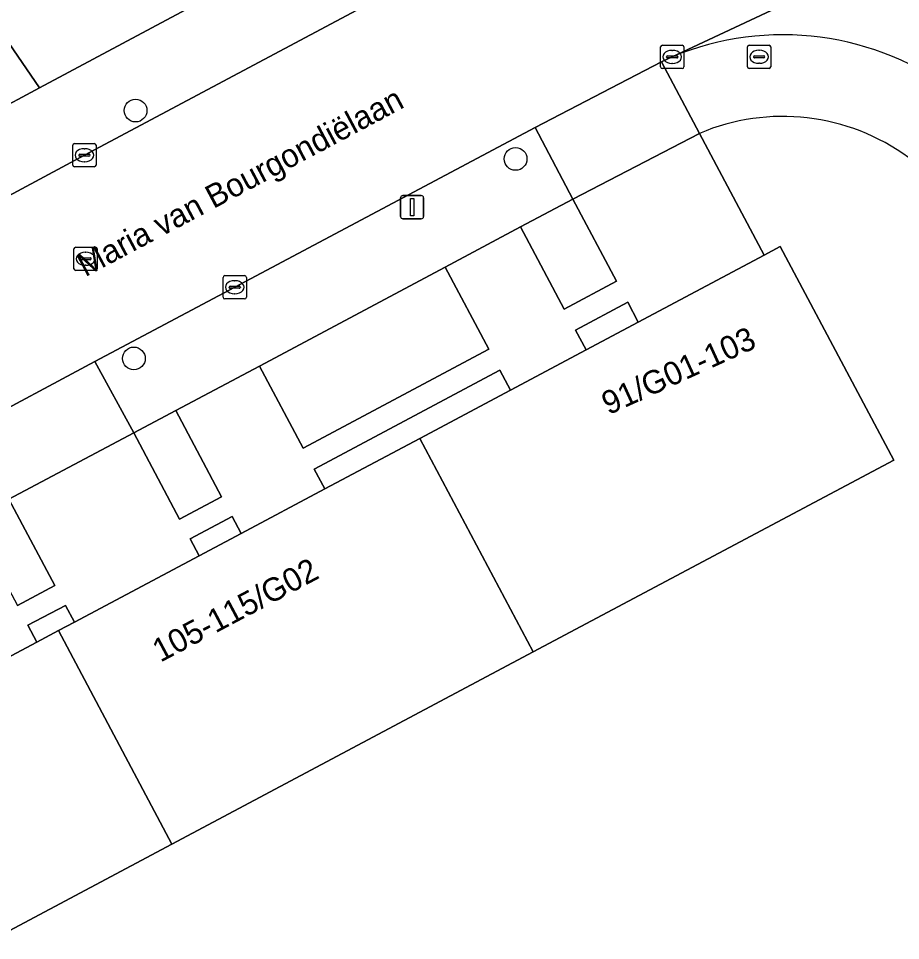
# Model space of a CAD drawing. Extents: x 159674 to 160531, y 382172 to 382904.
# Drawn here: x 159928.92 to 159966.84, y 382366.41 to 382406.07 of the extents above; entities that cross this region are included whole.
import ezdxf

# ---------------------------------------------------------------- set-up
doc = ezdxf.new("R2010")
doc.units = 0
for name, color, linetype in [('IMGEO_Boom', 7, 'Continuous'), ('IMGEO_Brandkraan', 7, 'Continuous'), ('IMGEO_Groenvoorziening', 7, 'Continuous'), ('IMGEO_Kolk', 7, 'Continuous'), ('IMGEO_Lichtmast', 7, 'Continuous'), ('IMGEO_Openbare_ruimte_label', 7, 'Continuous'), ('IMGEO_Pand', 7, 'Continuous'), ('IMGEO_Pand_nummerreeks', 7, 'Continuous'), ('IMGEO_Rijbaan_lokaal_gesloten', 7, 'Continuous'), ('IMGEO_Rioolput', 7, 'Continuous'), ('IMGEO_Voetpad_open', 7, 'Continuous')]:
    doc.layers.add(name, color=color, linetype=linetype)

msp = doc.modelspace()

# ---------------------------------------------------------------- linework, layer by layer
at = {"layer": 'IMGEO_Boom'}
for centre in [(159933.952, 382402.106), (159950.292, 382400.025), (159933.879, 382391.445)]:
    msp.add_circle(centre, 0.489, dxfattribs=at)
at = {"layer": 'IMGEO_Brandkraan'}
for p, q in [((159960.261, 382403.991), (159960.261, 382404.843)), ((159960.336, 382404.917), (159961.188, 382404.917)), ((159960.749, 382404.697), (159960.774, 382404.697)), ((159961.262, 382404.843), (159961.262, 382403.991)), ((159960.52, 382404.411), (159960.52, 382404.423)), ((159960.958, 382404.374), (159960.56, 382404.374)), ((159960.563, 382404.46), (159960.961, 382404.46)), ((159960.772, 382404.137), (159960.747, 382404.137)), ((159961.004, 382404.423), (159961.004, 382404.411)), ((159961.188, 382403.917), (159960.336, 382403.917))]:
    msp.add_line(p, q, dxfattribs=at)
for points in [[(159960.261, 382403.991), (159960.261, 382404.843)], [(159960.336, 382404.917), (159961.188, 382404.917)], [(159961.262, 382404.843), (159961.262, 382403.991)], [(159961.188, 382403.917), (159960.336, 382403.917)]]:
    msp.add_lwpolyline(points, dxfattribs=at)
for centre, radius, start, end in [((159960.338, 382404.841), 0.0765, 91.552, 178.448), ((159960.338, 382404.841), 0.0765, 91.552, 178.448), ((159961.186, 382404.841), 0.0765, 1.552, 88.448), ((159961.186, 382404.841), 0.0765, 1.552, 88.448), ((159960.56, 382404.42), 0.0403, 85.8775, 175.7526), ((159960.557, 382404.41), 0.0366, 178.938, 274.7102), ((159960.961, 382404.417), 0.043, 264.8664, 352.4533), ((159960.965, 382404.422), 0.0386, 1.7309, 96.639), ((159960.338, 382403.993), 0.0765, 181.552, 268.448), ((159960.338, 382403.993), 0.0765, 181.552, 268.448), ((159961.186, 382403.993), 0.0765, 271.552, 358.448), ((159961.186, 382403.993), 0.0765, 271.552, 358.448)]:
    msp.add_arc(centre, radius, start, end, dxfattribs=at)
for centre, major_axis, ratio, start_param, end_param in [((159960.748, 382404.417), (-0.387, 0.002), 0.722429, 4.712389, 7.853982), ((159960.773, 382404.417), (-0.39, 0.002), 0.717154, 1.570796, 4.712389)]:
    msp.add_ellipse(centre, major_axis=major_axis, ratio=ratio, start_param=start_param, end_param=end_param, dxfattribs=at)
at = {"layer": 'IMGEO_Groenvoorziening'}
for points in [[(159955.44, 382416.75), (159955.991, 382417.045), (159953.124, 382421.28), (159950.501, 382419.66), (159948.899, 382419.082), (159945.985, 382419.215), (159943.804, 382419.772), (159942.878, 382420.872), (159946.034, 382422.993), (159943.31, 382427.066), (159927.098, 382416.171), (159922.827, 382413.3), (159929.814, 382403.078), (159938.215, 382407.586), (159941.502, 382409.297), (159944.408, 382410.851)], [(159952.751, 382398.301), (159950.504, 382397.103), (159952.383, 382393.571), (159954.631, 382394.768)], [(159949.139, 382391.845), (159947.26, 382395.375), (159939.275, 382391.119), (159941.151, 382387.594)], [(159955.567, 382393.008), (159955.113, 382393.862), (159952.865, 382392.666), (159953.319, 382391.812)], [(159950.075, 382390.086), (159949.62, 382390.939), (159941.633, 382386.689), (159942.087, 382385.835), (159946.172, 382388.009)], [(159935.677, 382389.202), (159933.872, 382388.24), (159935.846, 382384.531), (159937.651, 382385.492)], [(159928.509, 382385.387), (159926.887, 382384.546), (159928.87, 382380.819), (159930.483, 382381.677)], [(159938.488, 382383.92), (159938.103, 382384.643), (159936.297, 382383.682), (159936.682, 382382.959)], [(159931.319, 382380.106), (159930.935, 382380.828), (159929.322, 382379.97), (159929.706, 382379.247), (159930.634, 382379.741)]]:
    msp.add_lwpolyline(points, close=True, dxfattribs=at)
msp.add_lwpolyline([(159958.199, 382401.124), (159960.984, 382395.891), (159961.672, 382396.257), (159966.549, 382387.076), (159951.046, 382378.827), (159935.509, 382370.559), (159919.971, 382362.292), (159904.434, 382354.024), (159899.56, 382363.206), (159900.148, 382363.519), (159897.359, 382368.831), (159897.322, 382368.812), (159894.018, 382367.057), (159888.032, 382358.712), (159893.426, 382354.811), (159896.041, 382352.9), (159899.107, 382350.689), (159925.951, 382331.335), (159937.083, 382337.299), (159935.493, 382340.283), (159938.868, 382342.054)], dxfattribs=at)
msp.add_arc((159961.779, 382392.708), 9.146, 53.7219, 113.0455, dxfattribs=at)
at = {"layer": 'IMGEO_Kolk'}
for p, q in [((159956.526, 382403.988), (159956.526, 382404.84)), ((159956.601, 382404.914), (159957.453, 382404.914)), ((159957.014, 382404.694), (159957.039, 382404.694)), ((159957.527, 382404.84), (159957.527, 382403.988)), ((159956.785, 382404.408), (159956.785, 382404.42)), ((159957.223, 382404.371), (159956.825, 382404.371)), ((159956.828, 382404.457), (159957.226, 382404.457)), ((159957.037, 382404.134), (159957.012, 382404.134)), ((159957.269, 382404.42), (159957.269, 382404.408)), ((159957.453, 382403.914), (159956.601, 382403.914)), ((159931.251, 382399.761), (159931.251, 382400.613)), ((159931.326, 382400.687), (159932.178, 382400.687)), ((159932.252, 382400.613), (159932.252, 382399.761)), ((159931.51, 382400.181), (159931.51, 382400.193)), ((159931.553, 382400.23), (159931.951, 382400.23)), ((159931.739, 382400.467), (159931.764, 382400.467)), ((159931.994, 382400.193), (159931.994, 382400.181)), ((159931.948, 382400.144), (159931.55, 382400.144)), ((159931.762, 382399.907), (159931.737, 382399.907)), ((159932.178, 382399.687), (159931.326, 382399.687)), ((159937.713, 382394.081), (159937.713, 382394.933)), ((159937.788, 382395.007), (159938.64, 382395.007)), ((159938.201, 382394.787), (159938.226, 382394.787)), ((159938.714, 382394.933), (159938.714, 382394.081)), ((159937.972, 382394.501), (159937.972, 382394.513)), ((159938.41, 382394.464), (159938.012, 382394.464)), ((159938.015, 382394.55), (159938.413, 382394.55)), ((159938.224, 382394.227), (159938.199, 382394.227)), ((159938.456, 382394.513), (159938.456, 382394.501)), ((159938.64, 382394.007), (159937.788, 382394.007))]:
    msp.add_line(p, q, dxfattribs=at)
for points in [[(159956.526, 382403.988), (159956.526, 382404.84)], [(159956.601, 382404.914), (159957.453, 382404.914)], [(159957.527, 382404.84), (159957.527, 382403.988)], [(159957.453, 382403.914), (159956.601, 382403.914)], [(159931.251, 382399.761), (159931.251, 382400.613)], [(159931.326, 382400.687), (159932.178, 382400.687)], [(159932.252, 382400.613), (159932.252, 382399.761)], [(159932.178, 382399.687), (159931.326, 382399.687)], [(159937.713, 382394.081), (159937.713, 382394.933)], [(159937.788, 382395.007), (159938.64, 382395.007)], [(159938.714, 382394.933), (159938.714, 382394.081)], [(159938.64, 382394.007), (159937.788, 382394.007)]]:
    msp.add_lwpolyline(points, dxfattribs=at)
for centre, radius, start, end in [((159956.603, 382404.838), 0.0765, 91.552, 178.448), ((159956.603, 382404.838), 0.0765, 91.552, 178.448), ((159957.451, 382404.838), 0.0765, 1.552, 88.448), ((159957.451, 382404.838), 0.0765, 1.552, 88.448), ((159956.825, 382404.417), 0.0403, 85.8775, 175.7526), ((159956.822, 382404.407), 0.0366, 178.938, 274.7102), ((159957.226, 382404.414), 0.043, 264.8664, 352.4533), ((159957.23, 382404.419), 0.0386, 1.7309, 96.639), ((159956.603, 382403.99), 0.0765, 181.552, 268.448), ((159956.603, 382403.99), 0.0765, 181.552, 268.448), ((159957.451, 382403.99), 0.0765, 271.552, 358.448), ((159957.451, 382403.99), 0.0765, 271.552, 358.448), ((159931.328, 382400.611), 0.0765, 91.552, 178.448), ((159931.328, 382400.611), 0.0765, 91.552, 178.448), ((159932.176, 382400.611), 0.0765, 1.552, 88.448), ((159932.176, 382400.611), 0.0765, 1.552, 88.448), ((159931.55, 382400.19), 0.0403, 85.8775, 175.7526), ((159931.547, 382400.18), 0.0366, 178.938, 274.7102), ((159931.951, 382400.187), 0.043, 264.8664, 352.4533), ((159931.955, 382400.192), 0.0386, 1.7309, 96.639), ((159931.328, 382399.763), 0.0765, 181.552, 268.448), ((159931.328, 382399.763), 0.0765, 181.552, 268.448), ((159932.176, 382399.763), 0.0765, 271.552, 358.448), ((159932.176, 382399.763), 0.0765, 271.552, 358.448), ((159937.79, 382394.931), 0.0765, 91.552, 178.448), ((159937.79, 382394.931), 0.0765, 91.552, 178.448), ((159938.638, 382394.931), 0.0765, 1.552, 88.448), ((159938.638, 382394.931), 0.0765, 1.552, 88.448), ((159938.012, 382394.51), 0.0403, 85.8775, 175.7526), ((159938.009, 382394.5), 0.0366, 178.938, 274.7102), ((159938.413, 382394.507), 0.043, 264.8664, 352.4533), ((159938.417, 382394.512), 0.0386, 1.7309, 96.639), ((159937.79, 382394.083), 0.0765, 181.552, 268.448), ((159937.79, 382394.083), 0.0765, 181.552, 268.448), ((159938.638, 382394.083), 0.0765, 271.552, 358.448), ((159938.638, 382394.083), 0.0765, 271.552, 358.448)]:
    msp.add_arc(centre, radius, start, end, dxfattribs=at)
for centre, major_axis, ratio, start_param, end_param in [((159957.013, 382404.414), (-0.387, 0.002), 0.722429, 4.712389, 7.853982), ((159957.038, 382404.414), (-0.39, 0.002), 0.717154, 1.570796, 4.712389), ((159931.738, 382400.187), (-0.387, 0.002), 0.722429, 4.712389, 7.853982), ((159931.763, 382400.187), (-0.39, 0.002), 0.717154, 1.570796, 4.712389), ((159938.2, 382394.507), (-0.387, 0.002), 0.722429, 4.712389, 7.853982), ((159938.225, 382394.507), (-0.39, 0.002), 0.717154, 1.570796, 4.712389)]:
    msp.add_ellipse(centre, major_axis=major_axis, ratio=ratio, start_param=start_param, end_param=end_param, dxfattribs=at)
at = {"layer": 'IMGEO_Lichtmast'}
for p, q in [((159945.346, 382397.552), (159945.346, 382398.352)), ((159945.346, 382398.352), (159945.346, 382397.552)), ((159945.446, 382398.452), (159946.236, 382398.452)), ((159946.236, 382398.452), (159945.446, 382398.452)), ((159946.336, 382398.352), (159946.336, 382397.552)), ((159946.336, 382397.552), (159946.336, 382398.352)), ((159946.236, 382397.452), (159945.446, 382397.452)), ((159945.446, 382397.452), (159946.236, 382397.452))]:
    msp.add_line(p, q, dxfattribs=at)
msp.add_lwpolyline([(159945.766, 382398.327), (159945.916, 382398.327), (159945.916, 382397.577), (159945.766, 382397.577), (159945.766, 382398.327)], dxfattribs=at)
for centre, start, end in [((159945.446, 382398.352), 90, 180), ((159945.446, 382398.352), 90, 180), ((159946.236, 382398.352), 0, 90), ((159946.236, 382398.352), 360, 90), ((159945.446, 382397.552), 180, 270), ((159945.446, 382397.552), 180, 270), ((159946.236, 382397.552), 270, 0), ((159946.236, 382397.552), 270, 0)]:
    msp.add_arc(centre, 0.1, start, end, dxfattribs=at)
at = {"layer": 'IMGEO_Pand'}
for points in [[(159961.672, 382396.257), (159960.984, 382395.891), (159955.567, 382393.008), (159953.319, 382391.812), (159950.075, 382390.086), (159946.172, 382388.009), (159951.046, 382378.827), (159966.549, 382387.076)], [(159946.172, 382388.009), (159942.087, 382385.835), (159938.488, 382383.92), (159936.682, 382382.959), (159931.319, 382380.106), (159930.634, 382379.741), (159935.509, 382370.559), (159951.046, 382378.827)], [(159930.634, 382379.741), (159929.706, 382379.247), (159924.602, 382376.531), (159922.312, 382375.313), (159919.013, 382373.558), (159915.097, 382371.474), (159919.971, 382362.292), (159935.509, 382370.559)]]:
    msp.add_lwpolyline(points, close=True, dxfattribs=at)
at = {"layer": 'IMGEO_Rijbaan_lokaal_gesloten'}
msp.add_lwpolyline([(159956.561, 382404.202), (159957.027, 382404.415), (159971.594, 382411.249), (159963.588, 382417.082), (159951.117, 382410.379), (159948.098, 382408.904), (159931.751, 382400.186), (159926.173, 382397.188), (159915.606, 382391.545), (159914.495, 382390.981), (159906.798, 382386.87), (159910.565, 382379.779), (159919.315, 382384.424), (159920.172, 382384.892), (159925.235, 382387.585), (159926.838, 382388.444), (159932.202, 382391.318), (159938.214, 382394.508), (159951.131, 382401.378)], close=True, dxfattribs=at)
msp.add_lwpolyline([(160000, 382390.554), (159999.175, 382391.156), (159996.317, 382393.238), (159977.556, 382406.905), (159976.539, 382407.646), (159971.594, 382411.249), (159957.027, 382404.415)], dxfattribs=at)
msp.add_arc((159961.781, 382393.016), 12.35, 52.3754, 112.6374, dxfattribs=at)
at = {"layer": 'IMGEO_Rioolput'}
for p, q in [((159931.377, 382396.23), (159932.229, 382396.23)), ((159931.302, 382395.304), (159931.302, 382396.156)), ((159931.79, 382396.01), (159931.815, 382396.01)), ((159932.303, 382396.156), (159932.303, 382395.304)), ((159931.561, 382395.724), (159931.561, 382395.736)), ((159931.999, 382395.687), (159931.601, 382395.687)), ((159931.604, 382395.773), (159932.002, 382395.773)), ((159931.813, 382395.45), (159931.788, 382395.45)), ((159932.045, 382395.736), (159932.045, 382395.724)), ((159932.229, 382395.23), (159931.377, 382395.23))]:
    msp.add_line(p, q, dxfattribs=at)
for points in [[(159931.377, 382396.23), (159932.229, 382396.23)], [(159931.302, 382395.304), (159931.302, 382396.156)], [(159932.303, 382396.156), (159932.303, 382395.304)], [(159932.229, 382395.23), (159931.377, 382395.23)]]:
    msp.add_lwpolyline(points, dxfattribs=at)
for centre, radius, start, end in [((159931.379, 382396.154), 0.0765, 91.552, 178.448), ((159931.379, 382396.154), 0.0765, 91.552, 178.448), ((159932.227, 382396.154), 0.0765, 1.552, 88.448), ((159932.227, 382396.154), 0.0765, 1.552, 88.448), ((159931.601, 382395.733), 0.0403, 85.8775, 175.7526), ((159931.598, 382395.723), 0.0366, 178.938, 274.7102), ((159932.002, 382395.73), 0.043, 264.8664, 352.4533), ((159932.006, 382395.735), 0.0386, 1.7309, 96.639), ((159931.379, 382395.306), 0.0765, 181.552, 268.448), ((159931.379, 382395.306), 0.0765, 181.552, 268.448), ((159932.227, 382395.306), 0.0765, 271.552, 358.448), ((159932.227, 382395.306), 0.0765, 271.552, 358.448)]:
    msp.add_arc(centre, radius, start, end, dxfattribs=at)
for centre, major_axis, ratio, start_param, end_param in [((159931.789, 382395.73), (-0.387, 0.002), 0.722429, 4.712389, 7.853982), ((159931.814, 382395.73), (-0.39, 0.002), 0.717154, 1.570796, 4.712389)]:
    msp.add_ellipse(centre, major_axis=major_axis, ratio=ratio, start_param=start_param, end_param=end_param, dxfattribs=at)
at = {"layer": 'IMGEO_Voetpad_open'}
for points in [[(159918.425, 382419.817), (159903.89, 382410.089), (159905.803, 382407.165), (159913.445, 382412.281), (159915.158, 382409.723), (159920.134, 382413.023), (159927.732, 382401.96), (159929.814, 382403.078), (159922.827, 382413.3), (159927.098, 382416.171), (159943.31, 382427.066), (159947.463, 382429.844), (159946.768, 382430.917), (159946.127, 382430.485), (159944.129, 382429.142), (159922.12, 382414.349)], [(159951.131, 382401.378), (159952.751, 382398.301), (159958.199, 382401.124), (159956.561, 382404.202)], [(159947.26, 382395.375), (159950.504, 382397.103), (159952.751, 382398.301), (159951.131, 382401.378), (159938.214, 382394.508), (159932.202, 382391.318), (159933.872, 382388.24), (159935.677, 382389.202), (159939.275, 382391.119)], [(159926.838, 382388.444), (159928.509, 382385.387), (159933.872, 382388.24), (159932.202, 382391.318)]]:
    msp.add_lwpolyline(points, close=True, dxfattribs=at)
for points in [[(159964.863, 382421.789), (159961.663, 382420.078), (159960.402, 382419.404), (159955.991, 382417.045), (159955.44, 382416.75), (159944.408, 382410.851), (159941.502, 382409.297), (159938.215, 382407.586), (159929.814, 382403.078), (159927.732, 382401.96), (159924.556, 382400.256), (159914.132, 382394.686), (159914.011, 382394.622), (159912.019, 382393.591), (159909.248, 382392.109), (159908.813, 382391.876), (159907.181, 382391.009), (159903.975, 382389.305), (159889.684, 382381.711)], [(159931.751, 382400.186), (159948.098, 382408.904), (159951.117, 382410.379), (159963.588, 382417.082), (159967.119, 382418.98)], [(159957.027, 382404.415), (159956.561, 382404.202), (159958.199, 382401.124)], [(159924.602, 382376.531), (159929.706, 382379.247), (159929.322, 382379.97), (159930.935, 382380.828), (159931.319, 382380.106), (159936.682, 382382.959), (159936.297, 382383.682), (159938.103, 382384.643), (159938.488, 382383.92), (159942.087, 382385.835), (159941.633, 382386.689), (159949.62, 382390.939), (159950.075, 382390.086), (159953.319, 382391.812), (159952.865, 382392.666), (159955.113, 382393.862), (159955.567, 382393.008), (159960.984, 382395.891), (159958.199, 382401.124), (159952.751, 382398.301), (159954.631, 382394.768), (159952.383, 382393.571), (159950.504, 382397.103), (159947.26, 382395.375), (159949.139, 382391.845), (159941.151, 382387.594), (159939.275, 382391.119), (159935.677, 382389.202), (159937.651, 382385.492), (159935.846, 382384.531), (159933.872, 382388.24), (159928.509, 382385.387), (159930.483, 382381.677), (159928.87, 382380.819)], [(159889.919, 382377.867), (159897.21, 382381.749), (159906.798, 382386.87), (159914.495, 382390.981), (159915.606, 382391.545), (159926.173, 382397.188), (159931.751, 382400.186)]]:
    msp.add_lwpolyline(points, dxfattribs=at)
for centre, radius, start, end in [((159961.781, 382393.016), 12.35, 52.3754, 112.6374), ((159961.779, 382392.708), 9.146, 53.7219, 113.0455)]:
    msp.add_arc(centre, radius, start, end, dxfattribs=at)

# ---------------------------------------------------------------- texts
at = {"layer": 'IMGEO_Openbare_ruimte_label'}
msp.add_text('Maria van Bourgondiëlaan', height=1, rotation=28.0253, dxfattribs=at).set_placement((159931.787, 382394.934))
at = {"layer": 'IMGEO_Pand_nummerreeks'}
for s, rotation, p in [('91/G01-103', 24.5684, (159954.288, 382389)), ('105-115/G02', 28.0176, (159935.022, 382378.36))]:
    msp.add_text(s, height=1, rotation=rotation, dxfattribs=at).set_placement(p)

doc.saveas('drawing.dxf')
